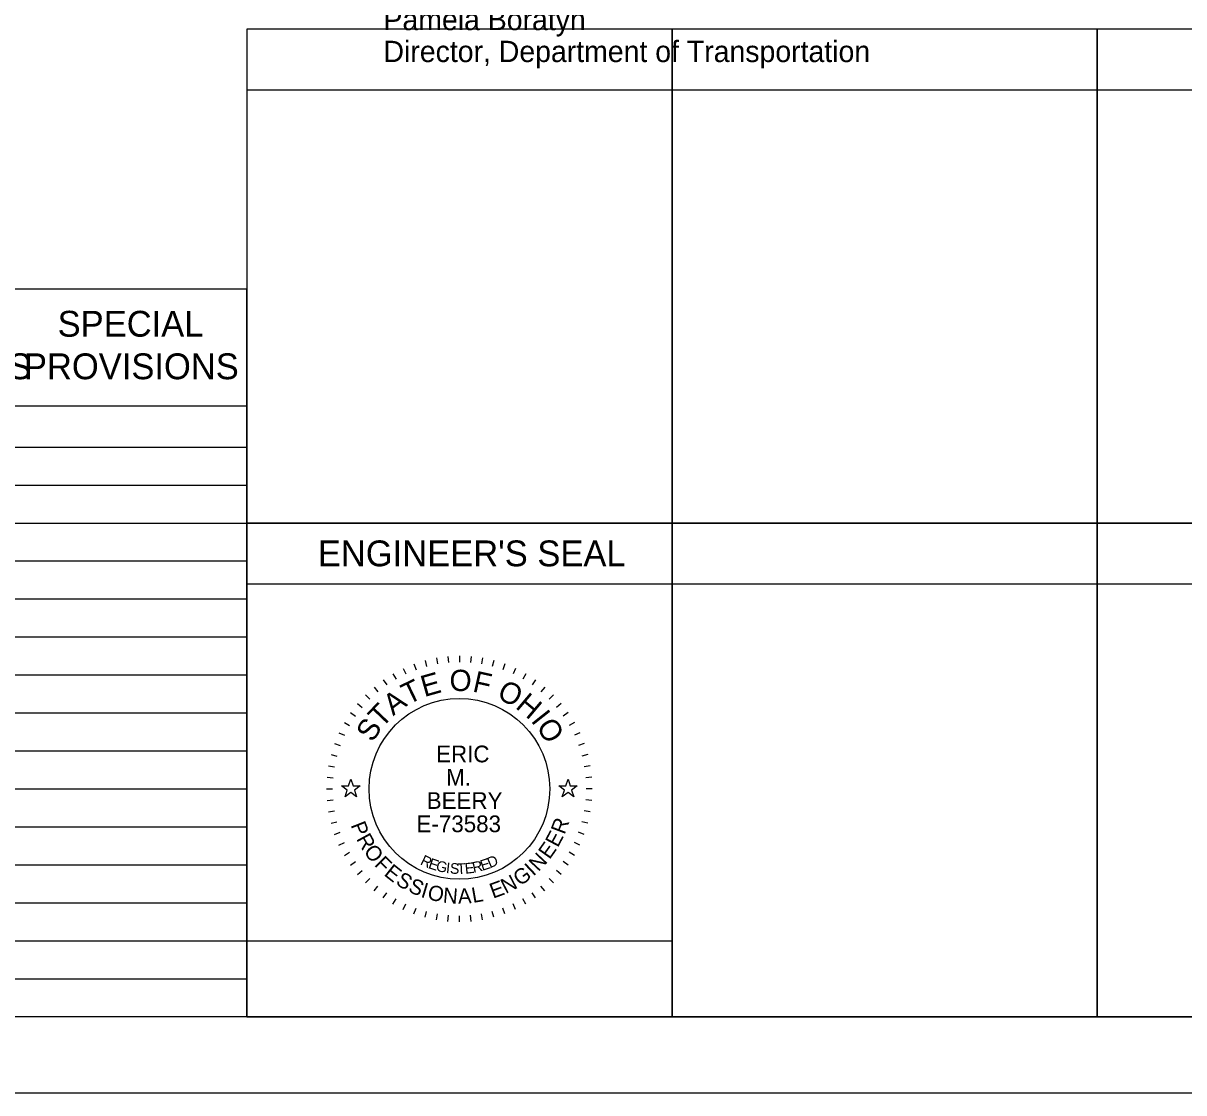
# Model space of a CAD drawing. Extents: x 0 to 34, y 0 to 22.
# Drawn here: x 22.13 to 29.77, y 0 to 7.04 of the extents above; entities that cross this region are included whole.
import ezdxf

# ---------------------------------------------------------------- set-up
doc = ezdxf.new("R2010")
doc.units = 0
for name, color, linetype in [('SH_Border', 7, 'Continuous'), ('SH_Cut_Line', 7, 'Continuous'), ('SH_Data', 7, 'Continuous'), ('SH_Seal', 7, 'Continuous'), ('SH_Text', 7, 'Continuous')]:
    doc.layers.add(name, color=color, linetype=linetype)

msp = doc.modelspace()

# ---------------------------------------------------------------- linework, layer by layer
at = {"layer": 'SH_Border'}
msp.add_lwpolyline([(1.5, 21.5), (33.5, 21.5), (33.5, 0.5), (1.5, 0.5)], close=True, dxfattribs=at)
at = {"layer": 'SH_Cut_Line'}
msp.add_lwpolyline([(0, 0), (34, 0), (34, 22), (0, 22)], close=True, dxfattribs=at)
at = {"layer": 'SH_Data'}
for p, q in [((23.6, 6.6), (26.4, 6.6)), ((26.4, 6.6), (29.2, 6.6)), ((29.2, 6.6), (32, 6.6)), ((10.15, 5.2917), (23.6, 5.2917)), ((23.6, 0.5), (23.6, 5.2917)), ((10.15, 4.5209), (23.6, 4.5209)), ((10.15, 4.25), (23.6, 4.25)), ((10.15, 4), (23.6, 4)), ((10.15, 3.75), (23.6, 3.75)), ((23.6, 0.5), (23.6, 3.75)), ((23.6, 3.75), (26.4, 3.75)), ((26.4, 3.75), (26.4, 0.5)), ((10.15, 3.5), (23.6, 3.5)), ((23.6, 3.35), (26.4, 3.35)), ((23.6, 3.35), (26.4, 3.35)), ((26.4, 3.35), (29.2, 3.35)), ((29.2, 3.35), (32, 3.35)), ((10.15, 3.25), (23.6, 3.25)), ((10.15, 3), (23.6, 3)), ((10.15, 2.75), (23.6, 2.75)), ((10.15, 2.5), (23.6, 2.5)), ((10.15, 2.25), (23.6, 2.25)), ((10.15, 2), (23.6, 2)), ((10.15, 1.75), (23.6, 1.75)), ((10.15, 1.5), (23.6, 1.5)), ((10.15, 1.25), (23.6, 1.25)), ((10.15, 1), (23.6, 1)), ((10.15, 0.75), (23.6, 0.75)), ((23.6, 0.5), (26.4, 0.5))]:
    msp.add_line(p, q, dxfattribs=at)
for points in [[(26.4, 7), (23.6, 7), (23.6, 3.75), (26.4, 3.75)], [(29.2, 7), (26.4, 7), (26.4, 3.75), (29.2, 3.75)], [(32, 7), (29.2, 7), (29.2, 3.75), (32, 3.75)], [(26.4, 3.75), (23.6, 3.75), (23.6, 0.5), (26.4, 0.5)], [(29.2, 3.75), (26.4, 3.75), (26.4, 0.5), (29.2, 0.5)], [(32, 3.75), (29.2, 3.75), (29.2, 0.5), (32, 0.5)], [(23.6, 0.5), (23.6, 1), (26.4, 1), (26.4, 0.5)]]:
    msp.add_lwpolyline(points, close=True, dxfattribs=at)
at = {"layer": 'SH_Seal'}
for p, q in [((24.7735, 2.8452), (24.7839, 2.8065)), ((24.8481, 2.8617), (24.855, 2.8223)), ((24.9237, 2.8717), (24.9272, 2.8318)), ((25, 2.875), (25, 2.835)), ((25.0763, 2.8717), (25.0728, 2.8318)), ((25.1519, 2.8617), (25.145, 2.8223)), ((25.2265, 2.8452), (25.2161, 2.8065)), ((24.5625, 2.7578), (24.5825, 2.7231)), ((24.6302, 2.793), (24.6471, 2.7568)), ((24.7007, 2.8222), (24.7144, 2.7846)), ((25.2993, 2.8222), (25.2856, 2.7846)), ((25.3698, 2.793), (25.3529, 2.7568)), ((25.4375, 2.7578), (25.4175, 2.7231)), ((24.4981, 2.7168), (24.5211, 2.684)), ((25.5019, 2.7168), (25.4789, 2.684)), ((24.3813, 2.6187), (24.4096, 2.5904)), ((24.4376, 2.6703), (24.4633, 2.6396)), ((25.5624, 2.6703), (25.5367, 2.6396)), ((25.6187, 2.6187), (25.5904, 2.5904)), ((24.3297, 2.5624), (24.3604, 2.5367)), ((25.6703, 2.5624), (25.6396, 2.5367)), ((24.2832, 2.5019), (24.316, 2.4789)), ((25.7168, 2.5019), (25.684, 2.4789)), ((24.207, 2.3698), (24.2432, 2.3529)), ((24.2422, 2.4375), (24.2769, 2.4175)), ((25.7578, 2.4375), (25.7231, 2.4175)), ((25.793, 2.3698), (25.7568, 2.3529)), ((24.1778, 2.2993), (24.2154, 2.2856)), ((25.8222, 2.2993), (25.7846, 2.2856)), ((24.1548, 2.2265), (24.1935, 2.2161)), ((25.8452, 2.2265), (25.8065, 2.2161)), ((24.1383, 2.1519), (24.1777, 2.145)), ((25.8617, 2.1519), (25.8223, 2.145)), ((24.1283, 2.0763), (24.1682, 2.0728)), ((25.8717, 2.0763), (25.8318, 2.0728)), ((24.125, 2), (24.165, 2)), ((25.875, 2), (25.835, 2)), ((24.1283, 1.9237), (24.1682, 1.9272)), ((25.8717, 1.9237), (25.8318, 1.9272)), ((24.1383, 1.8481), (24.1777, 1.855)), ((25.8617, 1.8481), (25.8223, 1.855)), ((24.1548, 1.7735), (24.1935, 1.7839)), ((25.8452, 1.7735), (25.8065, 1.7839)), ((24.1778, 1.7007), (24.2154, 1.7144)), ((25.8222, 1.7007), (25.7846, 1.7144)), ((24.207, 1.6302), (24.2432, 1.6471)), ((25.793, 1.6302), (25.7568, 1.6471)), ((24.2422, 1.5625), (24.2769, 1.5825)), ((25.7578, 1.5625), (25.7231, 1.5825)), ((24.2832, 1.4981), (24.316, 1.5211)), ((24.3297, 1.4376), (24.3604, 1.4633)), ((25.6703, 1.4376), (25.6396, 1.4633)), ((25.7168, 1.4981), (25.684, 1.5211)), ((24.3813, 1.3813), (24.4096, 1.4096)), ((25.6187, 1.3813), (25.5904, 1.4096)), ((24.4376, 1.3297), (24.4633, 1.3604)), ((24.4981, 1.2832), (24.5211, 1.316)), ((25.5019, 1.2832), (25.4789, 1.316)), ((25.5624, 1.3297), (25.5367, 1.3604)), ((24.5625, 1.2422), (24.5825, 1.2769)), ((24.6302, 1.207), (24.6471, 1.2432)), ((25.3698, 1.207), (25.3529, 1.2432)), ((25.4375, 1.2422), (25.4175, 1.2769)), ((24.7007, 1.1778), (24.7144, 1.2154)), ((24.7735, 1.1548), (24.7839, 1.1935)), ((24.8481, 1.1383), (24.855, 1.1777)), ((24.9237, 1.1283), (24.9272, 1.1682)), ((25, 1.125), (25, 1.165)), ((25.0763, 1.1283), (25.0728, 1.1682)), ((25.1519, 1.1383), (25.145, 1.1777)), ((25.2265, 1.1548), (25.2161, 1.1935)), ((25.2993, 1.1778), (25.2856, 1.2154))]:
    msp.add_line(p, q, dxfattribs=at)
for points in [[(24.2236, 2.02), (24.2705, 2.02), (24.285, 2.0645), (24.2995, 2.02), (24.3464, 2.02), (24.3085, 1.9924), (24.323, 1.9478), (24.285, 1.9754), (24.247, 1.9478), (24.2615, 1.9924)], [(25.6536, 2.02), (25.7005, 2.02), (25.715, 2.0645), (25.7295, 2.02), (25.7764, 2.02), (25.7385, 1.9924), (25.753, 1.9478), (25.715, 1.9754), (25.677, 1.9478), (25.6915, 1.9924)]]:
    msp.add_lwpolyline(points, close=True, dxfattribs=at)
msp.add_circle((25, 2), 0.595, dxfattribs=at)

# ---------------------------------------------------------------- texts
at = {"layer": 'SH_Data'}
msp.add_text("ENGINEER'S SEAL", height=0.17, dxfattribs=at).set_placement((24.0676, 3.465))
at = {"layer": 'SH_Seal'}
for s, height, rotation, p in [('E', 0.14, 15.75706, (24.7684, 2.6038)), ('O', 0.14, 359.78119, (24.9347, 2.6443)), ('F', 0.14, 347.43619, (25.0811, 2.6417)), ('T', 0.14, 25.71674, (24.6616, 2.5518)), ('O', 0.14, 332.25863, (25.2398, 2.6015)), ('A', 0.14, 36.47472, (24.5634, 2.4781)), ('H', 0.14, 319.91363, (25.3632, 2.5361)), ('T', 0.14, 46.4344, (24.4883, 2.3964)), ('S', 0.14, 57.19238, (24.4281, 2.3014)), ('I', 0.14, 308.36695, (25.4665, 2.4483)), ('O', 0.14, 303.14906, (25.5021, 2.4089)), ('P', 0.1, 291.49398, (24.2823, 1.7621)), ('R', 0.1, 69.23216, (25.6919, 1.6954)), ('R', 0.1, 298.73106, (24.319, 1.6717)), ('E', 0.1, 61.99508, (25.6476, 1.6098)), ('O', 0.1, 306.46664, (24.3655, 1.5883)), ('E', 0.1, 54.75801, (25.5933, 1.5314)), ('F', 0.1, 314.7068, (24.4343, 1.4983)), ('R', 0.07, 334.48695, (24.7375, 1.5051)), ('E', 0.07, 341.03996, (24.7906, 1.4801)), ('E', 0.07, 17.68363, (25.1498, 1.4602)), ('D', 0.07, 23.30524, (25.201, 1.477)), ('N', 0.1, 47.02243, (25.5202, 1.4508)), ('E', 0.1, 321.43929, (24.4978, 1.4348)), ('G', 0.07, 347.47515, (24.8414, 1.4618)), ('I', 0.07, 353.78581, (24.9091, 1.4468)), ('S', 0.07, 356.89262, (24.9358, 1.4429)), ('T', 0.07, 3.00609, (24.9857, 1.4387)), ('E', 0.07, 6.01169, (25.0389, 1.4412)), ('R', 0.07, 11.91844, (25.0925, 1.4474)), ('G', 0.1, 35.04687, (25.3981, 1.357)), ('I', 0.1, 43.28703, (25.4868, 1.4214)), ('S', 0.1, 328.67637, (24.5743, 1.3752)), ('S', 0.1, 335.91345, (24.6564, 1.3266)), ('I', 0.1, 343.15053, (24.7406, 1.2897)), ('E', 0.1, 20.07421, (25.2212, 1.277)), ('N', 0.1, 27.31129, (25.3045, 1.3075)), ('O', 0.1, 346.88592, (24.7839, 1.2751)), ('N', 0.1, 355.12608, (24.8888, 1.2517)), ('A', 0.1, 2.86166, (24.9923, 1.2437)), ('L', 0.1, 10.09874, (25.0894, 1.249))]:
    msp.add_text(s, height=height, rotation=rotation, dxfattribs=at).set_placement(p)
for s, p in [('ERIC', (24.8465, 2.1749)), ('M.', (24.9126, 2.0216)), ('BEERY', (24.7848, 1.8684)), ('E-73583', (24.7177, 1.7151))]:
    msp.add_text(s, height=0.11, dxfattribs=at).set_placement(p)
at = {"layer": 'SH_Text'}
for s, height, p in [('Pamela Boratyn', 0.14, (24.5, 6.9937)), ('Director, Department of Transportation', 0.14, (24.5, 6.7837)), ('SPECIAL', 0.17, (22.3542, 4.9763)), ('SPECIFICATIONS', 0.17, (20.2871, 4.6963)), ('PROVISIONS', 0.17, (22.1323, 4.6963))]:
    msp.add_text(s, height=height, dxfattribs=at).set_placement(p)

doc.saveas('drawing.dxf')
